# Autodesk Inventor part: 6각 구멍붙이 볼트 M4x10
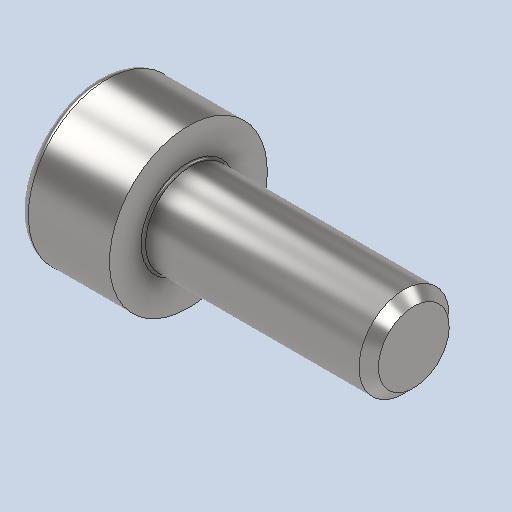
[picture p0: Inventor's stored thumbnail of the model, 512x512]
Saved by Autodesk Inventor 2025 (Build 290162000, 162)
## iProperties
Created: 2026-07
Part Number: 6각 구멍붙이 볼트 M4x10
Material: 강철, 연강
Description: 6각머리 태핑 나사
Document SubType Name: Modeling
Designer: KDI
Density: 7.85 g/cm^3
Appearance: 기본값
Author: jhkim
Sending System: Autodesk Inventor 2027
Preprocessor: ST-DEVELOPER v20.1
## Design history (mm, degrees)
feature "Solid1"
node "솔리드1"
